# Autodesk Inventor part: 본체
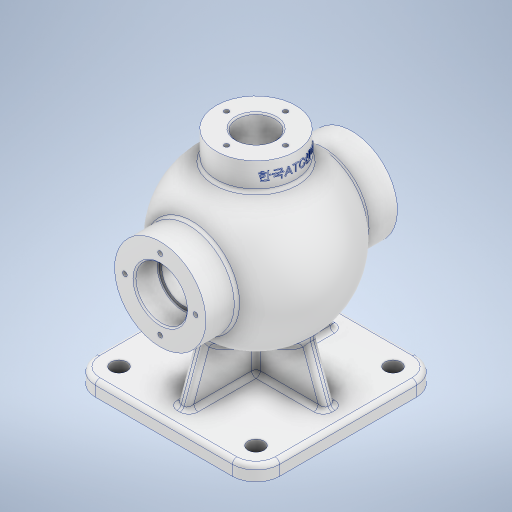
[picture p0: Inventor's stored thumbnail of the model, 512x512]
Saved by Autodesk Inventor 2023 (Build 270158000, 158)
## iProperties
Created: 2023-07
Part Number: 본체
Material: 알루미늄 6061
Document SubType Name: Modeling
Designer: Owner
Density: 2.7 g/cm^3
Appearance: 알루미늄 - 평지
Mass: 1526.65 g
Surface Area: 1174.15 cm^2
Volume: 565.427 cm^3
Author: Owner
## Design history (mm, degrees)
sketch "스케치3"
  geometry: L1 (-62.5, -62.5)-(62.5, -62.5); L2 (62.5, -62.5)-(62.5, 62.5); L3 (62.5, 62.5)-(-62.5, 62.5); L4 (-62.5, 62.5)-(-62.5, -62.5); L5 (-62.5, -62.5)-(62.5, 62.5); L6 (62.5, -62.5)-(-62.5, 62.5); 1 further point
  constraints: 12 end point, 2 midpoint, 2 parallel, 2 perpendicular, 1 horizontal
  dimensions: "d3" = 125 distance of L1.end L2.end
extrude "돌출1" new body sketch "스케치3" distance "d4" = 10; taper "d5" = 0 deg
sketch "스케치6"
  geometry: L1 (0, 62.5)-(0, -62.5) reference; L2 (85, 65)-(54, 65); L3 (54, -65)-(85, -65); L4 (85, -65)-(85, 65); L5 (85, 65)-(85, 54); L6 (85, -54)-(85, -65); L7 (54, 65)-(54, 44.215); L8 (54, -44.215)-(54, -65); L9 (85, 54)-(85, -54); A1 r 54 centre (85, 0) between (85, 54) and (85, -54); 8 further points
  constraints: 16 end point, 7 midpoint, 4 point on circle, 3 collinear, 3 parallel, 2 horizontal alignment, 2 perpendicular, 2 point on line, 1 centre point, 1 coincident, 1 horizontal
  dimensions: "d11" = 85 distance of point (0, 0) A1.centre; "d13" = 108 diameter of A1; "d14" = 130 distance of L2.end L3.start; "d15" = 31 distance from line of point (85, -59.5) L8; "d16" = 65 vertical distance of point (0, 0) point (69.5, 65)
revolve "회전2" sketch "스케치6" stored, may be unused: angle "d17" = 90 deg
sketch "스케치7"
  geometry: L1 (-62.5, 10)-(62.5, 10) reference; L2 (-50.5, 10)-(-23.202, 85); L3 (-62.5, 0)-(-62.5, 10) reference; L4 (62.5, 10)-(-62.5, 10) reference; L5 (50.5, 10)-(23.202, 85); L6 (62.5, 0)-(62.5, 10) reference; L7 (-23.202, 85)-(23.202, 85); L8 (62.5, 0)-(-62.5, 0) reference; C1 r 54 at (0, 85) reference; 5 further points
  constraints: 6 end point, 2 point on line, 1 horizontal, 1 midpoint
  dimensions: "d18" = 12 distance of L2.start L1.start; "d19" = 20 deg angle of L3 L2; "d20" = 12 distance of L1.end L5.start; "d22" = 20 deg angle of L6 L5; "d35" = 85 distance between parallel lines of L8 L7
extrude "돌출2" join sketch "스케치7" stored distance "d23" = 8; taper "d24" = 0 deg
sketch "스케치8"
  geometry: L1 (49.129, 36.258)-(10, 50.5); L2 (10, 62.5)-(10, -62.5) reference; L3 (0, 62.5)-(10, 62.5) reference; 1 further point
  constraints: 2 end point, 1 point on line
  dimensions: "d25" = 12 distance from line of L3 L1.end; "d26" = 20 deg angle of L3 L1
feature "리브2" sketch "스케치8" dims "d36" = 1, "d37" = 8, "d38" = 0, "d39" = 0, "d40" = 1, "d41" = 1
sketch "스케치9"
  geometry: C1 r 31 at (0, 0) reference; 2 further points
  constraints: 1 coincident
hole "구멍1" sketch "스케치9" at (0, 0) diameter "d42" = 30; stored, may be unused: countersink angle "d46" = 90 deg, drill point angle "d48" = 118 deg; dims "d43" = 4.4, "d44" = 35, "d45" = 16, "d47" = 7
sketch "스케치10"
  geometry: C1 r 31 at (0, 0) reference; 2 further points
  constraints: 1 coincident
hole "구멍2" sketch "스케치10" at (0, 0) diameter "d49" = 30; stored, may be unused: countersink angle "d53" = 90 deg, drill point angle "d55" = 118 deg; dims "d50" = 6, "d51" = 35, "d52" = 16, "d54" = 8
node "작업 평면1"
sketch "스케치11"
  geometry: C1 r 27 at (0, 0); 1 further point
  constraints: 1 centre point, 1 coincident
  dimensions: "d57" = 54 diameter of C1
extrude "돌출3" join sketch "스케치11" stored distance "d58" = 8; taper "d59" = 0 deg
sketch "스케치12"
  geometry: L1 (85, 44)-(85, -44); A1 r 54 centre (85, 0) between (46.034, -37.385) and (46.034, 37.385) reference; A2 r 44 centre (85, 0) between (85, -44) and (85, 44); 2 further points
  constraints: 2 coincident, 2 end point, 2 point on circle, 1 centre point, 1 midpoint, 1 vertical
  dimensions: "d60" = 88 diameter of A2
revolve "회전3" sketch "스케치12" stored, may be unused: angle "d61" = 90 deg
sketch "스케치13"
  geometry: C1 r 27 at (0, 0) reference; 2 further points
  constraints: 1 coincident
hole "구멍3" sketch "스케치13" at (0, 0) diameter "d62" = 26; stored, may be unused: countersink angle "d66" = 90 deg, drill point angle "d68" = 118 deg; dims "d63" = 6, "d64" = 35, "d65" = 16, "d67" = 8
sketch "스케치14"
  geometry: C1 r 13 at (0, 0) reference; 1 further point
  constraints: 1 vertical alignment
  dimensions: "d69" = 20 distance of C1.centre point (0, 20)
hole "구멍4" sketch "스케치14" at (0, 20) diameter "d70" = 3.242; stored, may be unused: countersink angle "d74" = 90 deg, drill point angle "d76" = 118 deg; dims "d71" = 8, "d72" = 4, "d73" = 2, "d75" = 11.8
sketch "스케치15"
  geometry: C1 r 17.5 at (0, 0) reference; 2 further points
  constraints: 1 vertical alignment
  dimensions: "d80" = 24 distance of C1.centre point (0, 24)
hole "구멍5" sketch "스케치15" at (0, 24) diameter "d81" = 3.242; stored, may be unused: countersink angle "d85" = 90 deg, drill point angle "d87" = 118 deg; dims "d82" = 12, "d83" = 4, "d84" = 2, "d86" = 15
fillet "모깎기3" dims "d91" = 16
fillet "모깎기4" dims "d92" = 3
fillet "모깎기5" dims "d93" = 3
fillet "모깎기6" dims "d94" = 3
chamfer "모따기1" distance "d95" = 1; stored, may be unused: second distance "d96" = 2, angle "d97" = 45 deg
fillet "모깎기7" dims "d98" = 0.6
sketch "스케치16"
  geometry: C1 r 5.5 at (-46.5, -46.5); A1 r 16 centre (-46.5, -46.5) between (-62.5, -46.5) and (-46.5, -62.5) reference; 1 further point
  constraints: 1 centre point, 1 coincident
  dimensions: "d99" = 11 diameter of C1
extrude "돌출4" cut sketch "스케치16" extent not by distance; stored distance "d100" = 10; taper "d101" = 0 deg
fillet "모깎기8" dims "d102" = 3
node "작업 평면2"
sketch "스케치17"
  geometry: L1 (0, -27)-(0, 27) reference; L2 (-150, 46.5)-(-150, -46.5) reference; 3 further points
  constraints: 1 horizontal alignment, 1 midpoint, 1 other
  dimensions: "d106" = 9 distance from line of L1 point (-9, 0)
feature "엠보싱1" sketch "스케치17" dims "d3" = 125, "d103" = 0.5, "d104" = 0
fillet "모깎기9" dims "d105" = 3
feature "̟耀̡耀̣耀̥耀̧耀̩耀̫耀̭耀" dims "d3" = 125, "d4" = 10, "d5" = 0, "d11" = 85, "d12" = 31, "d13" = 108, "d14" = 130, "d15" = 31, "d16" = 65, "d17" = 90 deg, "d18" = 12, "d19" = 20 deg, "d20" = 12, "d22" = 20 deg, "d23" = 8, "d24" = 0, "d25" = 12, "d26" = 20 deg, "d35" = 85, "d36" = 1, "d37" = 8, "d38" = 0, "d39" = 0, "d40" = 1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
node "솔리드2"
mirror "미러2"
pattern_circular "원형 패턴1" dims angle "d78" = 360 deg
pattern_circular "원형 패턴2" dims angle "d89" = 360 deg
mirror "미러3"
mirror "미러4"
mirror "미러5"
feature "A9D066F2-1C7D-4E18-AEED-F7BC21143FA4" dims "d42" = 30, "d43" = 4.4, "d44" = 35, "d45" = 16, "d46" = 90 deg, "d47" = 7, "d48" = 118 deg
